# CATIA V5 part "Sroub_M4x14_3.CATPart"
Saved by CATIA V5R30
Part number: Sroub_M4x14_3
Definition: 2025_05_12_09_08_15_0880
Nomenclature: 2025_05_12_09_08_15_0880
Source: Unknown
Description: PART--DESC
Bounding box of the stored display mesh (mm): x -97.5 to -90.5, y -1.99 to 4.99, z -5 to 9
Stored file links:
  E:\Bakalarka\Model\Forma_v7\Sroub_M4x14_3.CATPart
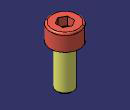
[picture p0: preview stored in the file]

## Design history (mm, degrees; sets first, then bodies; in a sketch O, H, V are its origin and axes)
Body1 "E2716_16B_NAUO2#E1200_4x10;Importiert1" (main body)
  Solid1: solid without history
